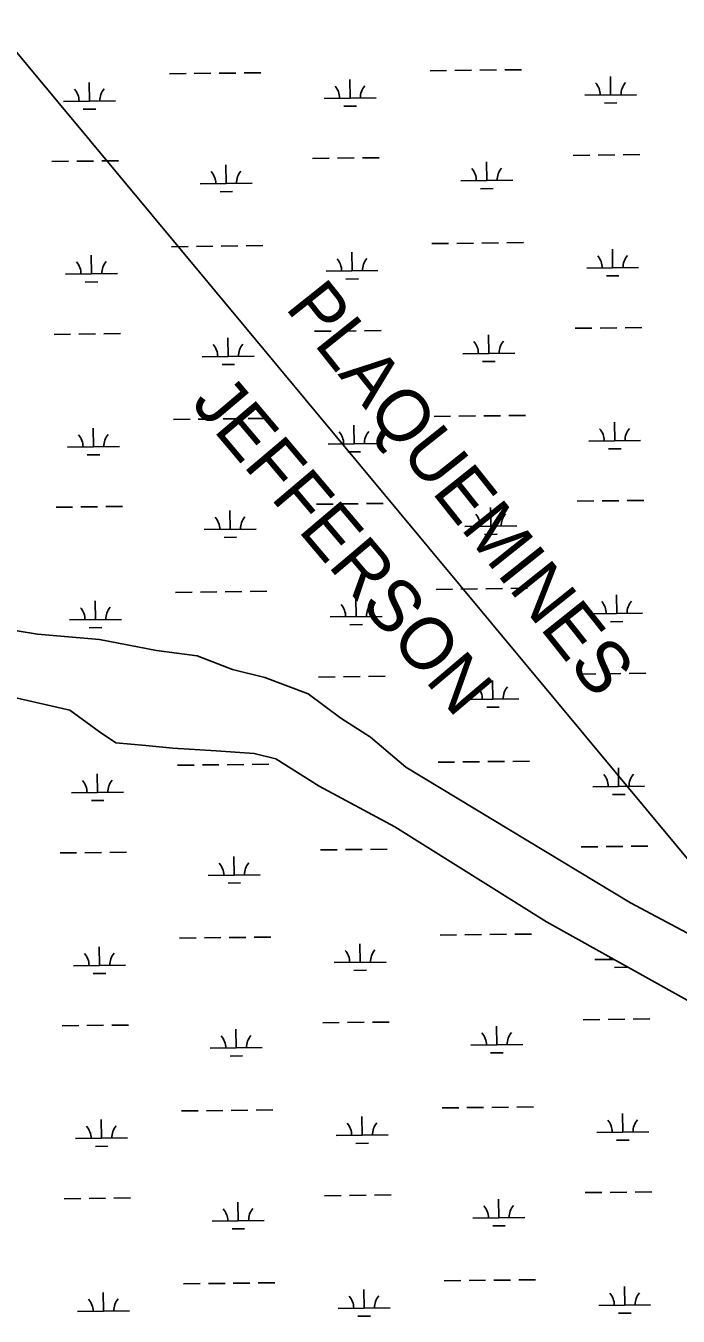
# Model space of a CAD drawing. Extents: x 3684037 to 3722149, y 433263 to 459021.
# Drawn here: x 3689441 to 3690697, y 441122 to 443605 of the extents above; entities that cross this region are included whole.
import ezdxf

# ---------------------------------------------------------------- set-up
doc = ezdxf.new("R2010")
doc.units = 0
for name, color, linetype in [('V-TOPO-BNDY', 7, 'Continuous'), ('V-TOPO-GNAM-IDEN', 7, 'Continuous'), ('V-TOPO-SHOR', 7, 'Continuous'), ('V-WETL-SWMP', 7, 'Continuous')]:
    doc.layers.add(name, color=color, linetype=linetype)

msp = doc.modelspace()

# ---------------------------------------------------------------- linework, layer by layer
at = {"layer": 'V-TOPO-BNDY'}
msp.add_line((3688191.4, 445033.4), (3691173.9, 441450.6), dxfattribs=at)
at = {"layer": 'V-TOPO-SHOR'}
for p, q in [((3689463.3, 442434.1), (3689301.6, 442460.1)), ((3689583.3, 442423.6), (3689463.3, 442434.1)), ((3689692.8, 442402.7), (3689583.3, 442423.6)), ((3689771, 442392.3), (3689692.8, 442402.7)), ((3689838.9, 442366.2), (3689771, 442392.3)), ((3689901.4, 442350.5), (3689838.9, 442366.2)), ((3689984.9, 442319.2), (3689901.4, 442350.5)), ((3689364.2, 442324.5), (3689525.9, 442287.9)), ((3690047.5, 442272.3), (3689984.9, 442319.2)), ((3689525.9, 442287.9), (3689583.3, 442246.2)), ((3690104.9, 442235.7), (3690047.5, 442272.3)), ((3689583.3, 442246.2), (3689614.6, 442225.3)), ((3690172.7, 442178.3), (3690104.9, 442235.7)), ((3689614.6, 442225.3), (3689672, 442220.1)), ((3689672, 442220.1), (3689724.1, 442214.9)), ((3689724.1, 442214.9), (3689807.6, 442209.6)), ((3689807.6, 442209.6), (3689880.6, 442204.4)), ((3689880.6, 442204.4), (3689922.3, 442194)), ((3689922.3, 442194), (3690005.8, 442141.8)), ((3690605.6, 441917.4), (3690172.7, 442178.3)), ((3690005.8, 442141.8), (3690151.8, 442063.5)), ((3690151.8, 442063.5), (3690443.9, 441880.8)), ((3690908.1, 441755.6), (3690605.6, 441917.4)), ((3690443.9, 441880.8), (3690845.5, 441656.4))]:
    msp.add_line(p, q, dxfattribs=at)
at = {"layer": 'V-WETL-SWMP'}
for p, q in [((3690219.5, 443518.3), (3690251.5, 443518.7)), ((3690267.5, 443518.9), (3690299.5, 443519.3)), ((3690315.5, 443519.5), (3690347.5, 443519.8)), ((3690363.5, 443520), (3690395.5, 443520.4)), ((3689563.6, 443460), (3689563.2, 443496)), ((3689717.6, 443512.5), (3689749.6, 443512.9)), ((3689765.6, 443513.1), (3689797.6, 443513.4)), ((3689813.6, 443513.6), (3689845.6, 443514)), ((3689861.6, 443514.2), (3689893.6, 443514.6)), ((3690065.5, 443465.8), (3690065.1, 443501.8)), ((3690567.3, 443471.6), (3690566.9, 443507.6)), ((3690517.4, 443471.1), (3690617.3, 443472.2)), ((3689513.6, 443459.4), (3689613.6, 443460.5)), ((3689551.8, 443444.4), (3689575.8, 443444.7)), ((3690015.5, 443465.2), (3690115.5, 443466.4)), ((3690053.7, 443450.2), (3690077.7, 443450.5)), ((3690555.5, 443456.1), (3690579.5, 443456.4)), ((3689539.5, 443344.2), (3689571.5, 443344.6)), ((3689587.5, 443344.8), (3689619.5, 443345.2)), ((3689993.4, 443349.5), (3690025.4, 443349.9)), ((3690041.4, 443350.1), (3690073.4, 443350.5)), ((3690089.4, 443350.6), (3690121.4, 443351)), ((3690495.3, 443355.4), (3690527.3, 443355.7)), ((3690543.3, 443355.9), (3690575.3, 443356.3)), ((3690591.3, 443356.5), (3690623.3, 443356.9)), ((3689491.5, 443343.7), (3689523.5, 443344.1)), ((3689826.9, 443301.2), (3689826.5, 443337.2)), ((3690328.8, 443307), (3690328.4, 443343)), ((3689776.9, 443300.6), (3689876.9, 443301.7)), ((3690278.8, 443306.4), (3690378.8, 443307.6)), ((3689815.1, 443285.6), (3689839.1, 443285.9)), ((3690317, 443291.4), (3690341, 443291.7)), ((3689721.5, 443179.8), (3689753.5, 443180.2)), ((3689769.5, 443180.4), (3689801.5, 443180.8)), ((3689817.5, 443181), (3689849.5, 443181.3)), ((3689865.5, 443181.5), (3689897.4, 443181.9)), ((3690223.3, 443185.7), (3690255.3, 443186.1)), ((3690271.3, 443186.2), (3690303.3, 443186.6)), ((3690319.3, 443186.8), (3690351.3, 443187.2)), ((3690367.3, 443187.4), (3690399.3, 443187.7)), ((3690571.2, 443139), (3690570.8, 443175)), ((3689567.5, 443127.3), (3689567.1, 443163.3)), ((3690069.3, 443133.2), (3690068.9, 443169.2)), ((3689517.5, 443126.7), (3689617.5, 443127.9)), ((3690019.3, 443132.6), (3690119.3, 443133.7)), ((3690521.2, 443138.4), (3690621.2, 443139.6)), ((3690559.4, 443123.4), (3690583.4, 443123.7)), ((3689555.7, 443111.7), (3689579.6, 443112)), ((3690057.5, 443117.6), (3690081.5, 443117.9)), ((3690499.2, 443022.7), (3690531.2, 443023.1)), ((3690547.2, 443023.3), (3690579.2, 443023.6)), ((3690595.2, 443023.8), (3690627.2, 443024.2)), ((3689495.4, 443011), (3689527.4, 443011.4)), ((3689543.4, 443011.6), (3689575.4, 443012)), ((3689591.4, 443012.2), (3689623.4, 443012.5)), ((3689830.8, 442968.5), (3689830.4, 443004.5)), ((3689997.3, 443016.9), (3690029.3, 443017.2)), ((3690045.3, 443017.4), (3690077.3, 443017.8)), ((3690093.3, 443018), (3690125.3, 443018.4)), ((3690332.6, 442974.3), (3690332.2, 443010.3)), ((3690282.6, 442973.8), (3690382.6, 442974.9)), ((3689780.8, 442967.9), (3689880.8, 442969.1)), ((3689819, 442952.9), (3689843, 442953.2)), ((3690320.8, 442958.8), (3690344.8, 442959.1)), ((3689773.3, 442847.8), (3689805.3, 442848.1)), ((3689821.3, 442848.3), (3689853.3, 442848.7)), ((3689869.3, 442848.9), (3689901.3, 442849.2)), ((3690227.2, 442853), (3690259.2, 442853.4)), ((3690275.2, 442853.6), (3690307.2, 442854)), ((3690323.2, 442854.2), (3690355.2, 442854.5)), ((3690371.2, 442854.7), (3690403.2, 442855.1)), ((3689571.3, 442794.7), (3689570.9, 442830.7)), ((3689725.3, 442847.2), (3689757.3, 442847.6)), ((3690073.2, 442800.5), (3690072.8, 442836.5)), ((3690575.1, 442806.3), (3690574.7, 442842.3)), ((3690023.2, 442799.9), (3690123.2, 442801.1)), ((3690525.1, 442805.8), (3690625.1, 442806.9)), ((3689521.3, 442794.1), (3689621.3, 442795.2)), ((3689559.5, 442779.1), (3689583.5, 442779.4)), ((3690061.4, 442784.9), (3690085.4, 442785.2)), ((3690563.3, 442790.8), (3690587.3, 442791)), ((3689499.3, 442678.4), (3689531.3, 442678.8)), ((3689547.3, 442678.9), (3689579.3, 442679.3)), ((3689595.3, 442679.5), (3689627.3, 442679.9)), ((3690001.2, 442684.2), (3690033.2, 442684.6)), ((3690049.2, 442684.8), (3690081.2, 442685.2)), ((3690097.1, 442685.3), (3690129.1, 442685.7)), ((3690336.5, 442641.7), (3690336.1, 442677.7)), ((3690503, 442690.1), (3690535, 442690.4)), ((3690551, 442690.6), (3690583, 442691)), ((3690599, 442691.2), (3690631, 442691.6)), ((3689834.6, 442635.9), (3689834.2, 442671.8)), ((3689784.6, 442635.3), (3689884.6, 442636.4)), ((3690286.5, 442641.1), (3690386.5, 442642.3)), ((3690324.7, 442626.1), (3690348.7, 442626.4)), ((3689822.8, 442620.3), (3689846.8, 442620.6)), ((3689729.2, 442514.5), (3689761.2, 442514.9)), ((3689777.2, 442515.1), (3689809.2, 442515.5)), ((3689825.2, 442515.7), (3689857.2, 442516)), ((3689873.2, 442516.2), (3689905.2, 442516.6)), ((3690077.1, 442467.8), (3690076.7, 442503.8)), ((3690231.1, 442520.4), (3690263.1, 442520.8)), ((3690279.1, 442520.9), (3690311.1, 442521.3)), ((3690327.1, 442521.5), (3690359.1, 442521.9)), ((3690375.1, 442522.1), (3690407.1, 442522.4)), ((3690579, 442473.7), (3690578.5, 442509.7)), ((3689575.2, 442462), (3689574.8, 442498)), ((3689463.3, 442434.1), (3689301.6, 442460.1)), ((3689525.2, 442461.4), (3689625.2, 442462.6)), ((3690027.1, 442467.3), (3690127.1, 442468.4)), ((3690065.3, 442452.3), (3690089.3, 442452.6)), ((3690529, 442473.1), (3690629, 442474.3)), ((3690567.1, 442458.1), (3690591.1, 442458.4)), ((3689583.3, 442423.6), (3689463.3, 442434.1)), ((3689563.4, 442446.4), (3689587.4, 442446.7)), ((3689692.8, 442402.7), (3689583.3, 442423.6)), ((3689771, 442392.3), (3689692.8, 442402.7)), ((3689838.9, 442366.2), (3689771, 442392.3)), ((3689901.4, 442350.5), (3689838.9, 442366.2)), ((3690005, 442351.6), (3690037, 442351.9)), ((3690053, 442352.1), (3690085, 442352.5)), ((3690101, 442352.7), (3690133, 442353.1)), ((3690506.9, 442357.4), (3690538.9, 442357.8)), ((3690554.9, 442358), (3690586.9, 442358.3)), ((3690602.9, 442358.5), (3690634.9, 442358.9)), ((3689984.9, 442319.2), (3689901.4, 442350.5)), ((3690340.4, 442309), (3690340, 442345)), ((3689364.2, 442324.5), (3689525.9, 442287.9)), ((3690047.5, 442272.3), (3689984.9, 442319.2)), ((3690290.4, 442308.5), (3690390.4, 442309.6)), ((3689525.9, 442287.9), (3689583.3, 442246.2)), ((3690328.6, 442293.5), (3690352.6, 442293.7)), ((3690104.9, 442235.7), (3690047.5, 442272.3)), ((3689583.3, 442246.2), (3689614.6, 442225.3)), ((3690172.7, 442178.3), (3690104.9, 442235.7)), ((3689614.6, 442225.3), (3689672, 442220.1)), ((3689672, 442220.1), (3689724.1, 442214.9)), ((3689724.1, 442214.9), (3689807.6, 442209.6)), ((3689807.6, 442209.6), (3689880.6, 442204.4)), ((3689880.6, 442204.4), (3689922.3, 442194)), ((3689733.1, 442181.9), (3689765.1, 442182.3)), ((3689781.1, 442182.5), (3689813.1, 442182.8)), ((3689829.1, 442183), (3689861.1, 442183.4)), ((3689877.1, 442183.6), (3689909.1, 442183.9)), ((3689922.3, 442194), (3690005.8, 442141.8)), ((3690605.6, 441917.4), (3690172.7, 442178.3)), ((3690234.9, 442187.7), (3690266.9, 442188.1)), ((3690282.9, 442188.3), (3690314.9, 442188.7)), ((3690330.9, 442188.8), (3690362.9, 442189.2)), ((3690378.9, 442189.4), (3690410.9, 442189.8)), ((3689579.1, 442129.4), (3689578.7, 442165.4)), ((3690582.8, 442141), (3690582.4, 442177)), ((3689529.1, 442128.8), (3689629.1, 442129.9)), ((3690005.8, 442141.8), (3690151.8, 442063.5)), ((3690532.8, 442140.5), (3690632.8, 442141.6)), ((3689567.3, 442113.8), (3689591.3, 442114.1)), ((3690571, 442125.5), (3690595, 442125.7)), ((3690151.8, 442063.5), (3690443.9, 441880.8)), ((3689507, 442013.1), (3689539, 442013.4)), ((3689555, 442013.6), (3689587, 442014)), ((3689603, 442014.2), (3689635, 442014.6)), ((3689842.4, 441970.5), (3689842, 442006.5)), ((3690008.9, 442018.9), (3690040.9, 442019.3)), ((3690056.9, 442019.5), (3690088.9, 442019.8)), ((3690104.9, 442020), (3690136.9, 442020.4)), ((3690510.8, 442024.8), (3690542.8, 442025.1)), ((3690558.8, 442025.3), (3690590.8, 442025.7)), ((3690606.8, 442025.9), (3690638.8, 442026.2)), ((3689792.4, 441970), (3689892.4, 441971.1)), ((3689830.6, 441955), (3689854.6, 441955.3)), ((3690908.1, 441755.6), (3690605.6, 441917.4)), ((3690443.9, 441880.8), (3690845.5, 441656.4)), ((3690238.8, 441855.1), (3690270.8, 441855.5)), ((3690286.8, 441855.6), (3690318.8, 441856)), ((3690334.8, 441856.2), (3690366.8, 441856.6)), ((3690382.8, 441856.8), (3690414.8, 441857.1)), ((3689583, 441796.7), (3689582.5, 441832.7)), ((3689736.9, 441849.2), (3689768.9, 441849.6)), ((3689784.9, 441849.8), (3689816.9, 441850.2)), ((3689832.9, 441850.4), (3689864.9, 441850.7)), ((3689880.9, 441850.9), (3689912.9, 441851.3)), ((3690084.8, 441802.5), (3690084.4, 441838.5)), ((3690536.7, 441807.8), (3690573.8, 441808.2)), ((3689533, 441796.1), (3689633, 441797.3)), ((3689571.1, 441781.1), (3689595.1, 441781.4)), ((3690034.8, 441802), (3690134.8, 441803.1)), ((3690073, 441787), (3690097, 441787.3)), ((3690574.9, 441792.8), (3690598.9, 441793.1)), ((3689510.9, 441680.4), (3689542.9, 441680.8)), ((3689558.9, 441681), (3689590.9, 441681.4)), ((3689606.9, 441681.5), (3689638.9, 441681.9)), ((3690012.8, 441686.3), (3690044.8, 441686.6)), ((3690060.8, 441686.8), (3690092.8, 441687.2)), ((3690108.8, 441687.4), (3690140.8, 441687.8)), ((3690514.6, 441692.1), (3690546.6, 441692.5)), ((3690562.6, 441692.7), (3690594.6, 441693)), ((3690610.6, 441693.2), (3690642.6, 441693.6)), ((3689846.3, 441637.9), (3689845.8, 441673.9)), ((3690348.1, 441643.7), (3690347.7, 441679.7)), ((3689796.3, 441637.3), (3689896.3, 441638.5)), ((3690298.1, 441643.2), (3690398.1, 441644.3)), ((3689834.4, 441622.3), (3689858.4, 441622.6)), ((3690336.3, 441628.2), (3690360.3, 441628.4)), ((3689740.8, 441516.6), (3689772.8, 441517)), ((3689788.8, 441517.1), (3689820.8, 441517.5)), ((3689836.8, 441517.7), (3689868.8, 441518.1)), ((3689884.8, 441518.3), (3689916.8, 441518.6)), ((3690242.7, 441522.4), (3690274.7, 441522.8)), ((3690290.7, 441523), (3690322.7, 441523.4)), ((3690338.7, 441523.5), (3690370.7, 441523.9)), ((3690386.7, 441524.1), (3690418.7, 441524.5)), ((3690590.6, 441475.7), (3690590.2, 441511.7)), ((3689586.8, 441464.1), (3689586.4, 441500)), ((3690088.7, 441469.9), (3690088.3, 441505.9)), ((3689536.8, 441463.5), (3689636.8, 441464.6)), ((3690038.7, 441469.3), (3690138.7, 441470.5)), ((3690540.6, 441475.1), (3690640.6, 441476.3)), ((3690578.8, 441460.2), (3690602.8, 441460.4)), ((3689575, 441448.5), (3689599, 441448.8)), ((3690076.9, 441454.3), (3690100.9, 441454.6)), ((3690518.5, 441359.5), (3690550.5, 441359.8)), ((3690566.5, 441360), (3690598.5, 441360.4)), ((3690614.5, 441360.6), (3690646.5, 441360.9)), ((3689514.8, 441347.8), (3689546.8, 441348.1)), ((3689562.8, 441348.3), (3689594.8, 441348.7)), ((3689610.8, 441348.9), (3689642.8, 441349.3)), ((3689850.1, 441305.2), (3689849.7, 441341.2)), ((3690016.6, 441353.6), (3690048.6, 441354)), ((3690064.6, 441354.2), (3690096.6, 441354.5)), ((3690112.6, 441354.7), (3690144.6, 441355.1)), ((3690352, 441311.1), (3690351.6, 441347.1)), ((3690302, 441310.5), (3690402, 441311.7)), ((3689800.1, 441304.7), (3689900.1, 441305.8)), ((3689838.3, 441289.7), (3689862.3, 441290)), ((3690340.2, 441295.5), (3690364.2, 441295.8)), ((3689744.7, 441183.9), (3689776.7, 441184.3)), ((3689792.7, 441184.5), (3689824.7, 441184.9)), ((3689840.7, 441185.1), (3689872.7, 441185.4)), ((3689888.7, 441185.6), (3689920.7, 441186)), ((3690246.6, 441189.8), (3690278.6, 441190.1)), ((3690294.6, 441190.3), (3690326.6, 441190.7)), ((3690342.6, 441190.9), (3690374.6, 441191.3)), ((3690390.6, 441191.5), (3690422.5, 441191.8)), ((3689590.7, 441131.4), (3689590.3, 441167.4)), ((3690092.6, 441137.2), (3690092.2, 441173.2)), ((3690594.4, 441143.1), (3690594, 441179.1)), ((3690042.6, 441136.7), (3690142.6, 441137.8)), ((3690544.4, 441142.5), (3690644.4, 441143.7)), ((3689540.7, 441130.8), (3689640.7, 441132)), ((3690080.8, 441121.7), (3690104.7, 441121.9)), ((3690582.6, 441127.5), (3690606.6, 441127.8))]:
    msp.add_line(p, q, dxfattribs=at)
for centre, start, end in [((3690512.1, 443471.5), 359.8949, 41.4385), ((3690622.6, 443472.8), 139.8949, 181.4385), ((3689508.4, 443459.8), 359.8949, 41.4385), ((3689618.8, 443461.1), 139.8949, 181.4385), ((3690010.2, 443465.6), 359.8949, 41.4385), ((3690120.7, 443466.9), 139.8949, 181.4385), ((3689771.7, 443301), 359.8949, 41.4385), ((3689882.1, 443302.3), 139.8949, 181.4385), ((3690273.5, 443306.8), 359.8949, 41.4385), ((3690384, 443308.1), 139.8949, 181.4385), ((3689512.2, 443127.1), 359.8949, 41.4385), ((3689622.7, 443128.4), 139.8949, 181.4385), ((3690014.1, 443133), 359.8949, 41.4385), ((3690124.6, 443134.3), 139.8949, 181.4385), ((3690516, 443138.8), 359.8949, 41.4385), ((3690626.5, 443140.1), 139.8949, 181.4385), ((3690277.4, 442974.2), 359.8949, 41.4385), ((3690387.9, 442975.5), 139.8949, 181.4385), ((3689775.5, 442968.3), 359.8949, 41.4385), ((3689886, 442969.6), 139.8949, 181.4385), ((3690018, 442800.3), 359.8949, 41.4385), ((3690128.4, 442801.6), 139.8949, 181.4385), ((3690519.8, 442806.2), 359.8949, 41.4385), ((3690630.3, 442807.5), 139.8949, 181.4385), ((3689516.1, 442794.5), 359.8949, 41.4385), ((3689626.6, 442795.8), 139.8949, 181.4385), ((3689779.4, 442635.7), 359.8949, 41.4385), ((3689889.9, 442637), 139.8949, 181.4385), ((3690281.3, 442641.5), 359.8949, 41.4385), ((3690391.8, 442642.8), 139.8949, 181.4385), ((3689520, 442461.8), 359.8949, 41.4385), ((3689630.4, 442463.1), 139.8949, 181.4385), ((3690021.8, 442467.7), 359.8949, 41.4385), ((3690132.3, 442469), 139.8949, 181.4385), ((3690523.7, 442473.5), 359.8949, 41.4385), ((3690634.2, 442474.8), 139.8949, 181.4385), ((3690285.1, 442308.9), 359.8949, 41.4385), ((3690395.6, 442310.2), 139.8949, 181.4385), ((3689523.8, 442129.2), 359.8949, 41.4385), ((3689634.3, 442130.5), 139.8949, 181.4385), ((3690527.6, 442140.9), 359.8949, 41.4385), ((3690638.1, 442142.2), 139.8949, 181.4385), ((3689787.1, 441970.4), 359.8949, 41.4385), ((3689897.6, 441971.7), 139.8949, 181.4385), ((3689527.7, 441796.5), 359.8949, 41.4385), ((3689638.2, 441797.8), 139.8949, 181.4385), ((3690029.6, 441802.4), 359.8949, 41.4385), ((3690140.1, 441803.7), 139.8949, 181.4385), ((3690531.5, 441808.2), 359.8949, 6.7543), ((3689791, 441637.7), 359.8949, 41.4385), ((3689901.5, 441639), 139.8949, 181.4385), ((3690292.9, 441643.6), 359.8949, 41.4385), ((3690403.4, 441644.9), 139.8949, 181.4385), ((3689531.6, 441463.9), 359.8949, 41.4385), ((3689642.1, 441465.2), 139.8949, 181.4385), ((3690033.5, 441469.7), 359.8949, 41.4385), ((3690143.9, 441471), 139.8949, 181.4385), ((3690535.3, 441475.6), 359.8949, 41.4385), ((3690645.8, 441476.8), 139.8949, 181.4385), ((3690296.8, 441310.9), 359.8949, 41.4385), ((3690407.2, 441312.2), 139.8949, 181.4385), ((3689794.9, 441305.1), 359.8949, 41.4385), ((3689905.4, 441306.4), 139.8949, 181.4385), ((3690037.3, 441137.1), 359.8949, 41.4385), ((3690147.8, 441138.4), 139.8949, 181.4385), ((3690539.2, 441142.9), 359.8949, 41.4385), ((3690649.7, 441144.2), 139.8949, 181.4385), ((3689535.5, 441131.2), 359.8949, 41.4385), ((3689645.9, 441132.5), 139.8949, 181.4385)]:
    msp.add_arc(centre, 35.2, start, end, dxfattribs=at)

# ---------------------------------------------------------------- texts
at = {"layer": 'V-TOPO-GNAM-IDEN'}
for s, rotation, p in [('PLAQUEMINES', 308.5266, (3689939, 443062.2)), ('JEFFERSON', 310.2271, (3689757.5, 442877.5))]:
    msp.add_text(s, height=100, rotation=rotation, dxfattribs=at).set_placement(p)

doc.saveas('drawing.dxf')
